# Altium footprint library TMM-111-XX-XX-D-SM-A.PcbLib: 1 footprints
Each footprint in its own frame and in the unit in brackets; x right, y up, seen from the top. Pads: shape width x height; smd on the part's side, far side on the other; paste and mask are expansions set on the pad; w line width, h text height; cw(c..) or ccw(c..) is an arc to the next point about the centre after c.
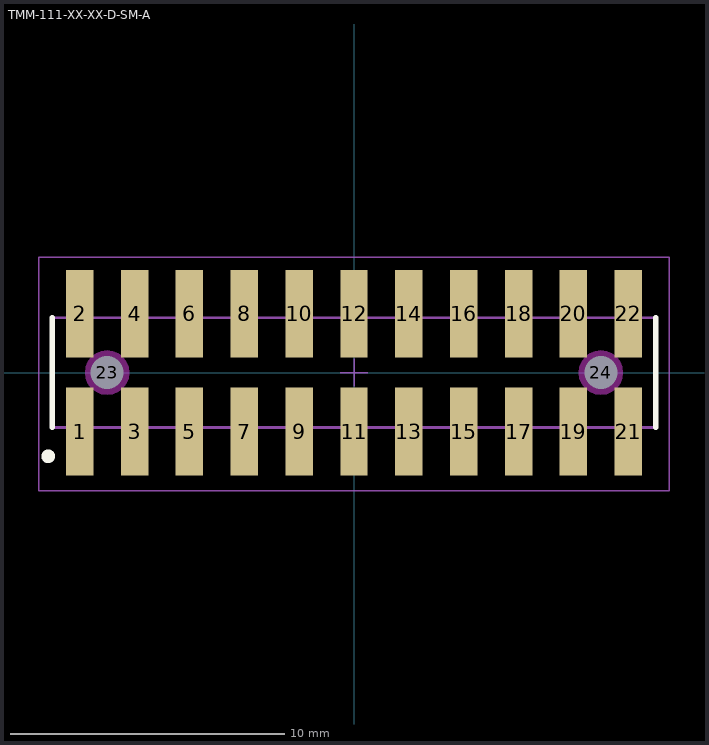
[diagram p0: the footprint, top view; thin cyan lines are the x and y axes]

## TMM-111-XX-XX-D-SM-A [mm] "2.00mm pitch, 22 pin, terminal strip; double row, w/alignment pins, SMT"
height 2.77
pads (24):
  rect 1x3.2 smd mask+0: 1(-10,-2.15) 2(-10,2.15) 3(-8,-2.15) 4(-8,2.15) 5(-6,-2.15) 6(-6,2.15) 7(-4,-2.15) 8(-4,2.15) 9(-2,-2.15) 10(-2,2.15) 11(0,-2.15) 12(0,2.15) 13(2,-2.15) 14(2,2.15) 15(4,-2.15) 16(4,2.15) 17(6,-2.15) 18(6,2.15) 19(8,-2.15) 20(8,2.15) 21(10,-2.15) 22(10,2.15)
  round 1 hole 1.2 unplated mask+0: 23(-9,0) 24(9,0)
Top Overlay:
  circle w0.25: c-11.15,-3.05 r0.125
  lines w0.2: -11,-2 -11,2 ; 11,-2 11,2
Keep-Out Layer:
  pour cut-out: 9.807,0 9.779,0.209 9.699,0.403 9.571,0.571 9.403,0.699 9.209,0.779 9,0.807 8.791,0.779 8.597,0.699 8.429,0.571 8.301,0.403 8.221,0.209 8.193,0 8.221,-0.209 8.301,-0.403 8.429,-0.571 8.597,-0.699 8.791,-0.779 9,-0.807 9.209,-0.779 9.403,-0.699 9.571,-0.571 9.699,-0.403 9.779,-0.209
  pour cut-out: -8.193,0 -8.221,0.209 -8.301,0.403 -8.429,0.571 -8.597,0.699 -8.791,0.779 -9,0.807 -9.209,0.779 -9.403,0.699 -9.571,0.571 -9.699,0.403 -9.779,0.209 -9.807,0 -9.779,-0.209 -9.699,-0.403 -9.571,-0.571 -9.403,-0.699 -9.209,-0.779 -9,-0.807 -8.791,-0.779 -8.597,-0.699 -8.429,-0.571 -8.301,-0.403 -8.221,-0.209
Mechanical 12:
  lines w0.001: -11,-2 -11,2 11,2 11,-2 -11,-2
Mechanical 13:
  lines w0.1: -11,-2 -11,2 11,2 11,-2 -11,-2
  text ".Designator" at 0,-0.127 h1.52
Mechanical 15:
  lines w0.05: -0.5,0 0.5,0 ; 0,-0.5 0,0.5 ; -11.5,-4.3 -11.5,4.2 11.5,4.2 11.5,-4.3 -11.5,-4.3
